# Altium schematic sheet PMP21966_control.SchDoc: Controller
size 431 x 279 mm; Date: Not shown in title block; ApprovedBy: Not shown in title block; CheckedBy: Not shown in title block; Author: Not shown in title block; CompanyName: Not shown in title block; DrawnBy: Tiger Z; Engineer: Not shown in title block; Organization: Not shown in title block; Address1: Not shown in title block; Address2: Not shown in title block; Address3: Not shown in title block; Address4: Not shown in title block; DocumentNumber: 5; Revision: Use project parameter SCH_Rev; SheetNumber: 1; SheetTotal: 3; PageSetup: Record=PageOptions¦CenterHorizontal=True¦CenterVertical=True¦PrintScale=1.00¦XCorrection=1.00¦YCorrection=1.00¦PrintKind=0¦BorderSize=5000000¦LeftOffset=0¦BottomOffset=0¦Orientation=2¦PaperLength=1000¦PaperWidth=1000¦Scale=100¦PaperSource=15¦PrintQuality=600¦MediaType=1¦DitherType=10¦PaperKind=Letter¦PrintScaleMode=1
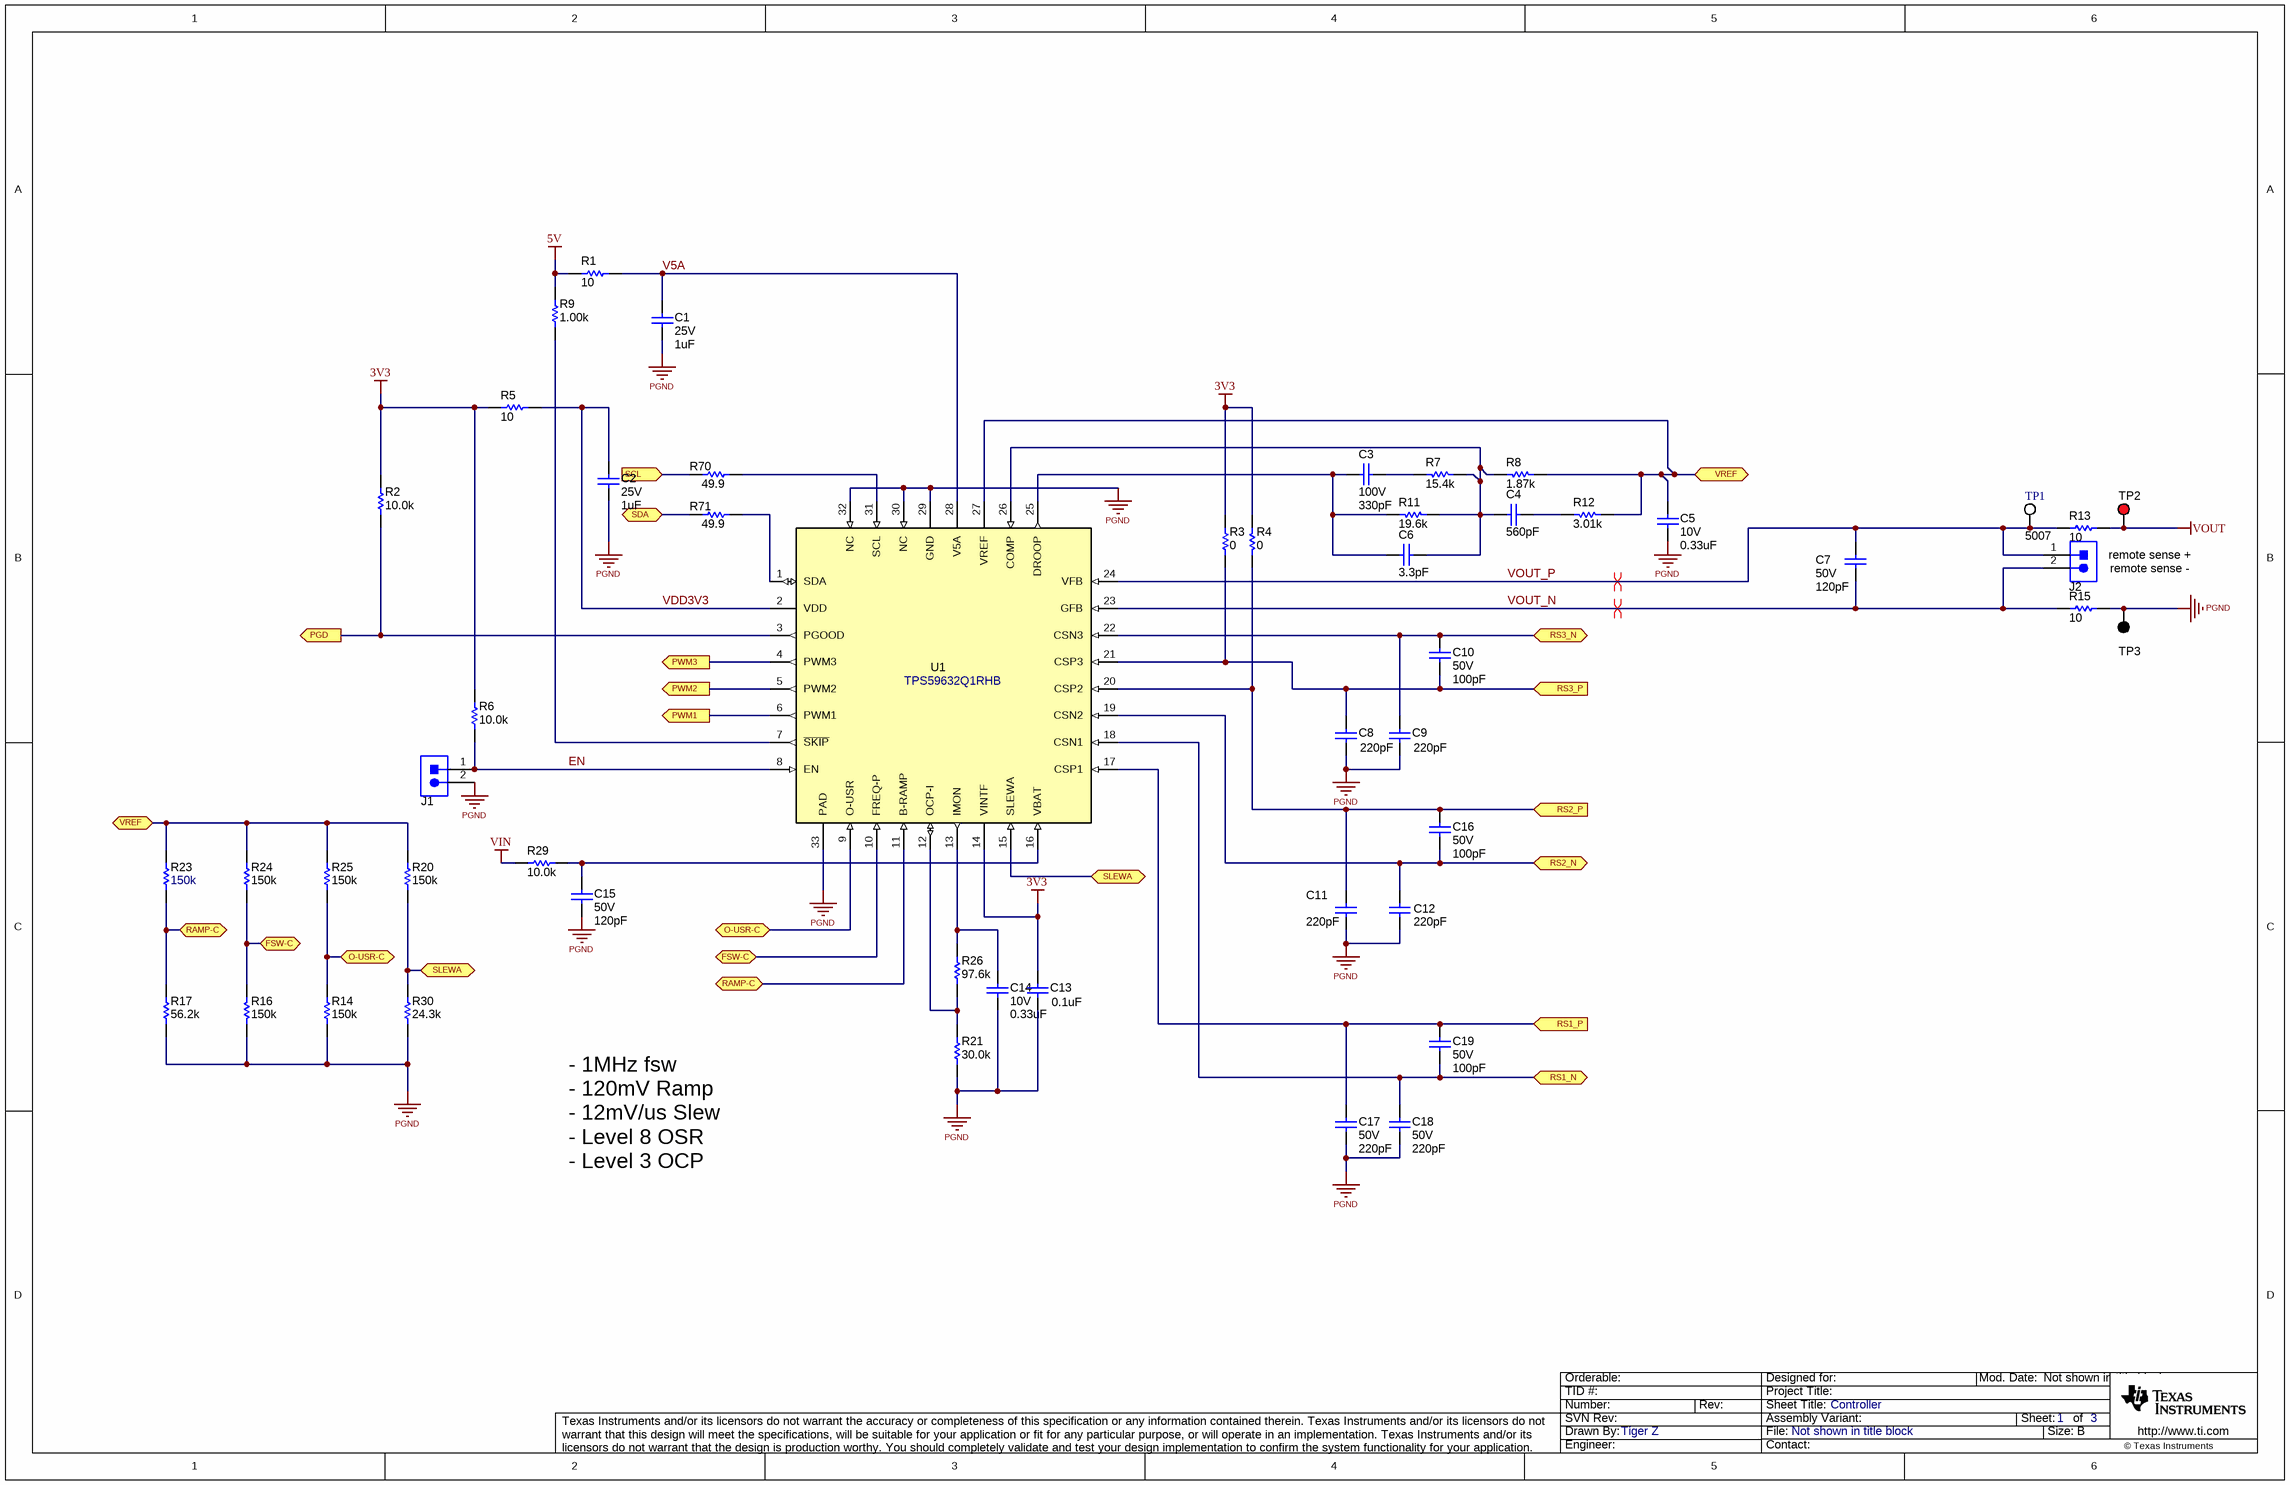
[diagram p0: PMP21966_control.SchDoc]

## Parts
C1  VDC_V: 25V  ValueDisplayed: 1uF  [0402S]  (hidden comment: GRM155R61E105KA12D)
C2  VDC_V: 25V  ValueDisplayed: 1uF  [0402S]  (hidden comment: GRM155R61E105KA12D)
C3  VDC_V: 100V  ValueDisplayed: 330pF  [0402S]  (hidden comment: GRM155R72A331KA01D)
C4  ValueDisplayed: 560pF  [0402S]  (hidden comment: GRM1555C1H561JA01D)
C5  VDC_V: 10V  ValueDisplayed: 0.33uF  [0402S]  (hidden comment: GRM155R61A334KE15D)
C6  ValueDisplayed: 3.3pF  [0402S]  (hidden comment: GRM1555C1E3R3CA01D)
C7  VDC_V: 50V  ValueDisplayed: 120pF  [0402S]  (hidden comment: GRM1555C1H121JA01D)
C8  ValueDisplayed: 220pF  [0402S]  (hidden comment: CGA2B2C0G1H221J050BA)
C9  ValueDisplayed: 220pF  [0402S]  (hidden comment: CGA2B2C0G1H221J050BA)
C10  VDC_V: 50V  ValueDisplayed: 100pF  [0402S]  (hidden comment: CC0402KRX7R9BB101)
C11  ValueDisplayed: 220pF  [0402S]  (hidden comment: CGA2B2C0G1H221J050BA)
C12  ValueDisplayed: 220pF  [0402S]  (hidden comment: CGA2B2C0G1H221J050BA)
C13  ValueDisplayed: 0.1uF  [0402S]  (hidden comment: CGA2B3X7R1H104K050BB)
C14  VDC_V: 10V  ValueDisplayed: 0.33uF  [0402S]  (hidden comment: GRM155R61A334KE15D)
C15  VDC_V: 50V  ValueDisplayed: 120pF  [0402S]  (hidden comment: GRM1555C1H121JA01D)
C16  VDC_V: 50V  ValueDisplayed: 100pF  [0402S]  (hidden comment: CC0402KRX7R9BB101)
C17  VDC_V: 50V  ValueDisplayed: 220pF  [0402S]  (hidden comment: CGA2B2C0G1H221J050BA)
C18  VDC_V: 50V  ValueDisplayed: 220pF  [0402S]  (hidden comment: CGA2B2C0G1H221J050BA)
C19  VDC_V: 50V  ValueDisplayed: 100pF  [0402S]  (hidden comment: CC0402KRX7R9BB101)
J1  HTSW-102-07-G-S  [Samtec_HTSW-102-07-G-S]  (value not drawn)
J2  HTSW-102-07-G-S  [Samtec_HTSW-102-07-G-S]  (value not drawn)
R1  ValueDisplayed: 10  [0402S]  (hidden comment: CRCW040210R0JNED)
R2  ValueDisplayed: 10.0k  [0402S]  (hidden comment: CRCW040210K0FKED)
R3  ValueDisplayed: 0  [0402S]  (hidden comment: CRCW04020000Z0ED)
R4  ValueDisplayed: 0  [0402S]  (hidden comment: CRCW04020000Z0ED)
R5  ValueDisplayed: 10  [0402S]  (hidden comment: CRCW040210R0JNED)
R6  ValueDisplayed: 10.0k  [0402S]  (hidden comment: CRCW040210K0FKED)
R7  ValueDisplayed: 15.4k  [0402S]  (hidden comment: CRCW040215K4FKED)
R8  Res_ohm: 1.87k  [0402S]  (hidden comment: CRCW04021K87FKED)
R9  ValueDisplayed: 1.00k  [0402S]  (hidden comment: CRCW04021K00FKED)
R11  ValueDisplayed: 19.6k  [0402S]  (hidden comment: CRCW040219K6FKED)
R12  ValueDisplayed: 3.01k  [0402S]  (hidden comment: CRCW04023K01FKED)
R13  ValueDisplayed: 10  [0402S]  (hidden comment: CRCW040210R0JNED)
R14  ValueDisplayed: 150k  [0402S]  (hidden comment: ERJ-2RKF1503X)
R15  ValueDisplayed: 10  [0402S]  (hidden comment: CRCW040210R0JNED)
R16  value 150k  [0402S]  (hidden comment: ERJ-2RKF1503X)
R17  ValueDisplayed: 56.2k  [0402S]  (hidden comment: CRCW040256K2FKED)
R20  ValueDisplayed: 150k  [0402S]  (hidden comment: ERJ-2RKF1503X)
R21  ValueDisplayed: 30.0k  [0402S]  (hidden comment: CRCW040230K0FKED)
R23  ValueDisplayed: 150k  [0402S]  (hidden comment: ERJ-2RKF1503X)
R24  ValueDisplayed: 150k  [0402S]  (hidden comment: ERJ-2RKF1503X)
R25  ValueDisplayed: 150k  [0402S]  (hidden comment: ERJ-2RKF1503X)
R26  ValueDisplayed: 97.6k  [0402S]  (hidden comment: CRCW040297K6FKED)
R29  ValueDisplayed: 10.0k  [0402S]  (hidden comment: CRCW040210K0FKED)
R30  ValueDisplayed: 24.3k  [0402S]  (hidden comment: CRCW040224K3FKED)
R70  ValueDisplayed: 49.9  [0402S]  (hidden comment: Resistor)
R71  ValueDisplayed: 49.9  [0402S]  (hidden comment: Resistor)
TP1  5007  [Keystone5002]
TP2  5000  [Keystone5000]  (value not drawn)
TP3  5001  [Keystone5001]  (value not drawn)
U1  TPS59632Q1RHB  [RSM0032B]

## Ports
FSW-C (bidir), O-USR-C (bidir), PGD (out), PWM1 (out), PWM2 (out), PWM3 (out), RAMP-C (bidir), RS1_N (bidir), RS1_P (in), RS2_N (bidir), RS2_P (in), RS3_N (bidir), RS3_P (in), SCL (in), SDA (bidir), SLEWA (bidir), VREF (bidir)

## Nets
3V3: C13.1 R2.2 R3.1 R4.1 R5.1 R6.2 U1.14(VINTF)
5V: R1.1 R9.2
PGND: C1.2 C2.2 C5.1 C8.1 C9.1 C11.2 C12.2 C13.2 C14.2 C15.1 C17.2 C18.2 J1.2 R14.1 R15.2 R16.2 R17.1 R21.1 R30.1 TP3.1 U1.29(GND) U1.30(NC) U1.32(NC) U1.33(PAD)
VIN: R29.1
VOUT: R13.2 TP2.1
EN: J1.1 R6.1 U1.8(EN)
FSW-C: R16.1 R24.1 U1.10(FREQ-P) ; port FSW-C
O-USR-C: R14.2 R25.1 U1.9(O-USR) ; port O-USR-C
PGD: R2.1 U1.3(PGOOD) ; port PGD
PWM1: U1.6(PWM1) ; port PWM1
PWM2: U1.5(PWM2) ; port PWM2
PWM3: U1.4(PWM3) ; port PWM3
RAMP-C: R17.2 R23.1 U1.11(B-RAMP) ; port RAMP-C
RS1_N: C18.1 C19.1 U1.18(CSN1) ; port RS1_N
RS1_P: C17.1 C19.2 U1.17(CSP1) ; port RS1_P
RS2_N: C12.1 C16.1 U1.19(CSN2) ; port RS2_N
RS2_P: C11.1 C16.2 R4.2 U1.20(CSP2) ; port RS2_P
RS3_N: C9.2 C10.2 U1.22(CSN3) ; port RS3_N
RS3_P: C8.2 C10.1 R3.2 U1.21(CSP3) ; port RS3_P
SCL: R70.1 ; port SCL
SDA: R71.1 ; port SDA
SLEWA: R20.1 R30.2 U1.15(SLEWA) ; port SLEWA
V5A: C1.1 R1.2 U1.28(V5A)
VDD3V3: C2.1 R5.2 U1.2(VDD)
VOUT_N: C7.2 J2.2 R15.1 U1.23(GFB)
VOUT_P: C7.1 J2.1 R13.1 TP1.1 U1.24(VFB)
VREF: C5.2 R8.2 R12.2 R20.2 R23.2 R24.2 R25.2 U1.27(VREF) ; port VREF
NetC3_1: C3.1 R7.2
NetC3_2: C3.2 C6.2 R11.1 U1.25(DROOP)
NetC4_1: C4.1 R12.1
NetC4_2: C4.2 C6.1 R7.1 R8.1 R11.2 U1.26(COMP)
NetC14_1: C14.1 R26.2 U1.13(IMON)
NetC15_2: C15.2 R29.2 U1.16(VBAT)
NetR9_1: R9.1 U1.7(~{SKIP})
NetR21_2: R21.2 R26.1 U1.12(OCP-I)
NetR70_2: R70.2 U1.31(SCL)
NetR71_2: R71.2 U1.1(SDA)

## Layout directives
differential pair: VOUT_N, VOUT_P

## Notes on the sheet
- remote sense +
- remote sense -
- - 1MHz fsw
  - 120mV Ramp
  - 12mV/us Slew
  - Level 8 OSR
  - Level 3 OCP

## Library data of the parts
C1 C2 = CMP-0006608-2: CAP, CERM, 1 uF, 25 V, +/- 10%, X5R, 0402; Manufacturer: MuRata; Cap_F: 1µF; SizeAreaWB_mm2: 3; SizeArea_mm2: 0.5; AEC Category: Q200; Value: 1uF; TaMax_C: 85°C; SizeZ_mm: 0.6; Polarized: N; TaMin_C: -55°C; U/M: EA; SizeX_mm: 1; Cap_Case: 0402; Value1: Unknown
C3 = CMP-0006707-2: CAP, CERM, 330 pF, 100 V, +/- 10%, X7R, 0402; Manufacturer: MuRata; SizeAreaWB_mm2: 3; SizeArea_mm2: 0.5; AEC Category: Q200; Value: 330pF; TaMax_C: 125°C; SizeZ_mm: 0.6; Polarized: N; TaMin_C: -55°C; U/M: EA; SizeX_mm: 1; Cap_Case: 0402; Value1: Unknown
C4 = CMP-0006479-2: CAP, CERM, 560 pF, 50 V, +/- 5%, C0G/NP0, 0402; Manufacturer: MuRata; TaMin_C: -55°C; Polarized: N; SizeAreaWB_mm2: 3; Value1: Unknown; U/M: EA; Value: 560pF; TaMax_C: 125°C; SizeZ_mm: 0.6; SizeX_mm: 1; SizeY_mm: 0.5; Cap_Case: 0402; Value2: 50V; CompType: Capacitor; AEC Category: Q200
C5 C14 = CMP-0006575-2: CAP, CERM, 0.33 uF, 10 V, +/- 10%, X5R, 0402; Manufacturer: MuRata; TaMin_C: -55°C; Polarized: N; SizeAreaWB_mm2: 3; Value1: Unknown; U/M: EA; Value: 0.33uF; TaMax_C: 85°C; SizeZ_mm: 0.6; SizeX_mm: 1; SizeY_mm: 0.5; Cap_Case: 0402; Cap_F: 330nF; AEC Category: Q200
C6 = CMP-0006383-2: CAP, CERM, 3.3 pF, 25 V, +/- 5%, C0G/NP0, 0402; Manufacturer: MuRata; TaMin_C: -55°C; Polarized: N; SizeAreaWB_mm2: 3; Value1: Unknown; U/M: EA; Value: 3.3pF; TaMax_C: 125°C; SizeZ_mm: 0.6; SizeX_mm: 1; SizeY_mm: 0.5; Cap_Case: 0402; Value2: 25V; CompType: Capacitor; AEC Category: Q200
C7 C15 = CMP-0006417-2: CAP, CERM, 120 pF, 50 V, +/- 5%, C0G/NP0, 0402; Manufacturer: MuRata; TaMin_C: -55°C; Polarized: N; SizeAreaWB_mm2: 3; Value1: Unknown; U/M: EA; Value: 120pF; TaMax_C: 125°C; SizeZ_mm: 0.6; SizeX_mm: 1; SizeY_mm: 0.5; Cap_Case: 0402; AEC Category: Q200
C8 C9 C11 C12 = CMP-0079606-1: CAP, CERM, 220 pF, 50 V,+/- 5%, C0G/NP0, AEC-Q200 Grade 1, 0402; Manufacturer: TDK; TaMin_C: -55°C; Polarized: N; SizeAreaWB_mm2: 3; U/M: EA; Value: 220pF; TaMax_C: 125°C; SizeZ_mm: 0.6; SizeX_mm: 1; SizeY_mm: 0.5; Cap_Case: 0402; Value2: 50V; CompType: Capacitor; AEC Qualified: Y; AEC Category: Q200
C10 C16 C19 = CMP-0006305-2: CAP, CERM, 100 pF, 50 V, +/- 10%, X7R, 0402; Manufacturer: Yageo America; TaMin_C: -55°C; Polarized: N; SizeAreaWB_mm2: 3; Value1: Unknown; U/M: EA; Value: 100pF; TaMax_C: 125°C; SizeZ_mm: 0.6; SizeX_mm: 1; SizeY_mm: 0.5; Cap_Case: 0402; AEC Category: Q200
C13 = CMP-0006325-2: CAP, CERM, 0.1 uF, 50 V, +/- 10%, X7R, AEC-Q200 Grade 1, 0402; Manufacturer: TDK; TaMin_C: -55°C; ESR_ohm: 0.039064; Polarized: N; SizeAreaWB_mm2: 3; Value1: 0.039064 ohm; U/M: EA; Value: 0.1uF; TaMax_C: 125°C; SizeZ_mm: 0.6; SizeX_mm: 1; SizeY_mm: 0.5; Cap_Case: 0402; Value2: 50V; CompType: Capacitor; AEC Qualified: Y; Cap_F: 100nF; IRMS_A: 8.14669dA; AEC Category: Q200
C17 = CMP-0079606-1: CAP, CERM, 220 pF, 50 V,+/- 5%, C0G/NP0, AEC-Q200 Grade 1, 0402; Manufacturer: TDK; TaMin_C: -55°C; Polarized: N; SizeAreaWB_mm2: 3; U/M: EA; Value: 220pF; TaMax_C: 125°C; SizeZ_mm: 0.6; SizeX_mm: 1; SizeY_mm: 0.5; Cap_Case: 0402; AEC Qualified: Y; AEC Category: Q200
C18 = CMP-0079606-1: CAP, CERM, 220 pF, 50 V,+/- 5%, C0G/NP0, AEC-Q200 Grade 1, 0402; Manufacturer: TDK; TaMin_C: -55°C; Polarized: N; SizeAreaWB_mm2: 3; U/M: EA; Value: 220pF; TaMax_C: 125°C; SizeZ_mm: 0.6; SizeX_mm: 1; SizeY_mm: 0.5; Cap_Case: 0402; CompType: Capacitor; AEC Qualified: Y; AEC Category: Q200
J1 J2 = CMP-0075483-1: Header, 100mil, 2x1, Gold, TH; Manufacturer: Samtec; Green_REACh: Passed; CT: False; Green_Lifecycle: Active; CNHeader: True
R1 R5 R13 R15 = CMP-0026827-3: RES, 10, 5%, 0.063 W, AEC-Q200 Grade 0, 0402; Manufacturer: Vishay-Dale; Power_W: 63mW; TempCo: 200 ppm/C; Value_Code: 10R0; Value: 10; EIA_Code: E24; SizeX_mm: 1; SizeY_mm: 0.5; SizeZ_mm: 0.6; Value2: 0.063W; AEC Qualified: Y; VDC_V: 50V; AEC Category: Q200; AEC Grade: 0
R2 = CMP-0025958-3: RES, 10.0 k, 1%, 0.063 W, AEC-Q200 Grade 0, 0402; Manufacturer: Vishay-Dale; Power_W: 63mW; TempCo: 100 ppm/C; Value_Code: 10k0; Value: 10.0k; EIA_Code: E96; Res_ohm: 10k; SizeX_mm: 1; SizeY_mm: 0.5; SizeZ_mm: 0.6; Value2: 0.063W; CompType: Resistor; AEC Qualified: Y; VDC_V: 50V; AEC Category: Q200; AEC Grade: 0
R3 R4 = CMP-0026822-3: RES, 0, 5%, 0.063 W, AEC-Q200 Grade 0, 0402; Manufacturer: Vishay-Dale; Power_W: 63mW; TempCo: 200 ppm/C; Value_Code: 0000; Value: 0; EIA_Code: E24; SizeX_mm: 1; SizeY_mm: 0.5; SizeZ_mm: 0.6; Value2: 0.063W; AEC Qualified: Y; VDC_V: 50V; AEC Category: Q200
R6 R29 = CMP-0025958-3: RES, 10.0 k, 1%, 0.063 W, AEC-Q200 Grade 0, 0402; Manufacturer: Vishay-Dale; Power_W: 63mW; TempCo: 100 ppm/C; Value_Code: 10k0; Value: 10.0k; EIA_Code: E96; Res_ohm: 10k; SizeX_mm: 1; SizeY_mm: 0.5; SizeZ_mm: 0.6; Value2: 0.063W; AEC Qualified: Y; VDC_V: 50V; AEC Category: Q200; AEC Grade: 0
R7 = CMP-0026028-3: RES, 15.4 k, 1%, 0.063 W, AEC-Q200 Grade 0, 0402; Manufacturer: Vishay-Dale; Power_W: 63mW; TempCo: 100 ppm/C; Value_Code: 15k4; Value: 15.4k; EIA_Code: E96; SizeX_mm: 1; SizeY_mm: 0.5; SizeZ_mm: 0.6; Value2: 0.063W; AEC Qualified: Y; VDC_V: 50V; AEC Grade: 0; AEC Category: Q200
R8 = CMP-0026097-2: RES, 1.87 k, 1%, 0.063 W, AEC-Q200 Grade 0, 0402; Manufacturer: Vishay-Dale; Power_W: 63mW; TempCo: 100 ppm/C; Value_Code: 1k87; Value: 1.87k; EIA_Code: E96; SizeX_mm: 1; SizeY_mm: 0.5; SizeZ_mm: 0.6; Value2: 0.063W; CompType: Resistor; AEC Qualified: Y; VDC_V: 50V; AEC Category: Q200; AEC Grade: 0
R9 = CMP-0026071-3: RES, 1.00 k, 1%, 0.063 W, AEC-Q200 Grade 0, 0402; Manufacturer: Vishay-Dale; Power_W: 63mW; TempCo: 100 ppm/C; Value_Code: 1k00; Value: 1.00k; EIA_Code: E96; Res_ohm: 1k; SizeX_mm: 1; SizeY_mm: 0.5; SizeZ_mm: 0.6; Value2: 0.063W; AEC Qualified: Y; VDC_V: 50V; AEC Category: Q200; AEC Grade: 0
R11 = CMP-0026068-3: RES, 19.6 k, 1%, 0.063 W, AEC-Q200 Grade 0, 0402; Manufacturer: Vishay-Dale; Power_W: 63mW; TempCo: 100 ppm/C; Value_Code: 19k6; Value: 19.6k; EIA_Code: E96; SizeX_mm: 1; SizeY_mm: 0.5; SizeZ_mm: 0.6; Value2: 0.063W; CompType: Resistor; AEC Qualified: Y; VDC_V: 50V; AEC Category: Q200; AEC Grade: 0
R12 = CMP-0026329-2: RES, 3.01 k, 1%, 0.063 W, AEC-Q200 Grade 0, 0402; Manufacturer: Vishay-Dale; Power_W: 63mW; TempCo: 100 ppm/C; Value_Code: 3k01; Value: 3.01k; EIA_Code: E96; SizeX_mm: 1; SizeY_mm: 0.5; SizeZ_mm: 0.6; Value2: 0.063W; AEC Qualified: Y; VDC_V: 50V; AEC Category: Q200; AEC Grade: 0
R14 = CMP-0026669-1: RES, 150 k, 1%, 0.1 W, AEC-Q200 Grade 0, 0402; Manufacturer: Panasonic; Power_W: 100mW; TempCo: 100 ppm/C; Value: 150k; EIA_Code: E96; SizeX_mm: 1; SizeY_mm: 0.5; SizeZ_mm: 0.6; Value2: 0.1W; AEC Qualified: Y; VDC_V: 50V; AEC Category: Q200; AEC Grade: 0; U/M: EA
R16 = CMP-0026669-1: RES, 150 k, 1%, 0.1 W, AEC-Q200 Grade 0, 0402; Manufacturer: Panasonic; Power_W: 100mW; TempCo: 100 ppm/C; U/M: EA; EIA_Code: E96; SizeX_mm: 1; SizeY_mm: 0.5; SizeZ_mm: 0.6; Value2: 0.1W; CompType: Resistor; AEC Qualified: Y; VDC_V: 50V; AEC Grade: 0; AEC Category: Q200
R17 = CMP-0026453-2: RES, 56.2 k, 1%, 0.063 W, AEC-Q200 Grade 0, 0402; Manufacturer: Vishay-Dale; Power_W: 63mW; TempCo: 100 ppm/C; Value_Code: 56k2; Value: 56.2k; EIA_Code: E96; SizeX_mm: 1; SizeY_mm: 0.5; SizeZ_mm: 0.6; Value2: 0.063W; AEC Qualified: Y; VDC_V: 50V; AEC Category: Q200; AEC Grade: 0
R20 R23 R25 = CMP-0026669-1: RES, 150 k, 1%, 0.1 W, AEC-Q200 Grade 0, 0402; Manufacturer: Panasonic; Power_W: 100mW; TempCo: 100 ppm/C; U/M: EA; Value: 150k; EIA_Code: E96; SizeX_mm: 1; SizeY_mm: 0.5; SizeZ_mm: 0.6; Value2: 0.1W; CompType: Resistor; AEC Qualified: Y; VDC_V: 50V; AEC Grade: 0; AEC Category: Q200
R21 = CMP-0078244-2: RES, 30.0 k, 1%, 0.063 W, AEC-Q200 Grade 0, 0402; Manufacturer: Vishay-Dale; Power_W: 63mW; TempCo: 100 ppm/C; Value_Code: 30k0; Value: 30.0k; Res_ohm: 30k; SizeX_mm: 1; SizeY_mm: 0.5; SizeZ_mm: 0.6; Value2: 0.063W; AEC Qualified: Y; VDC_V: 50V; AEC Category: Q200; AEC Grade: 0; Green_Lifecycle: Active; Green_REACh: Passed
R24 = CMP-0026669-1: RES, 150 k, 1%, 0.1 W, AEC-Q200 Grade 0, 0402; Manufacturer: Panasonic; Power_W: 100mW; TempCo: 100 ppm/C; U/M: EA; Value: 150k; EIA_Code: E96; SizeX_mm: 1; SizeY_mm: 0.5; SizeZ_mm: 0.6; Value2: 0.1W; AEC Qualified: Y; VDC_V: 50V; AEC Grade: 0; AEC Category: Q200
R26 = CMP-0026617-3: RES, 97.6 k, 1%, 0.063 W, AEC-Q200 Grade 0, 0402; Manufacturer: Vishay-Dale; Power_W: 63mW; TempCo: 100 ppm/C; Value_Code: 97k6; Value: 97.6k; EIA_Code: E96; SizeX_mm: 1; SizeY_mm: 0.5; SizeZ_mm: 0.6; Value2: 0.063W; AEC Qualified: Y; VDC_V: 50V; AEC Category: Q200; AEC Grade: 0
R30 = CMP-0026195-2: RES, 24.3 k, 1%, 0.063 W, AEC-Q200 Grade 0, 0402; Manufacturer: Vishay-Dale; Power_W: 63mW; TempCo: 100 ppm/C; Value_Code: 24k3; Value: 24.3k; EIA_Code: E96; SizeX_mm: 1; SizeY_mm: 0.5; SizeZ_mm: 0.6; Value2: 0.063W; CompType: Resistor; AEC Qualified: Y; VDC_V: 50V; AEC Category: Q200; AEC Grade: 0
R70 R71 = CMP-0026404-2: RES, 49.9, 1%, 0.063 W, AEC-Q200 Grade 0, 0402; PartNumber: CRCW040249R9FKED; Manufacturer: Vishay-Dale; Value: 49.9; Value_Code: 49R9; Power_W: 63mW; Value2: 0.063W; VDC_V: 50V; TempCo: 100 ppm/C; EIA_Code: E96; SizeArea_mm2: 0.5; SizeX_mm: 1; SizeZ_mm: 0.6; AEC Category: Q200; AEC Qualified: Y; AEC Grade: 0
TP1 = CMP-0055139-1: Test Point, Miniature, White, TH; Manufacturer: Keystone; CNHeader: FALSE; Green_Lifecycle: Active; Green_REACh: Passed; ContactFinish: Silver; CT: TRUE
TP2 = CMP-0055137-1: Test Point, Miniature, Red, TH; Manufacturer: Keystone; CNHeader: FALSE; Green_Lifecycle: Active; Green_REACh: Passed; ContactFinish: Silver; CT: TRUE
TP3 = CMP-0055138-1: Test Point, Miniature, Black, TH; Manufacturer: Keystone; CNHeader: FALSE; ContactFinish: Silver; CT: TRUE; Green_Lifecycle: Active; Green_REACh: Passed
U1 = CMP-0013985-3: 3-2-1 Phase D-Cap+ Step-Down Driverless Controller for Tegra CPUs with Serial VID Control and DVFS, RSM0032B (VQFN-32); Alternate Manufacturer: Texas Instruments; SizeAreaWB_mm2: 25; SizeZ_mm: 1; SizeX_mm: 4; SizeArea_mm2: 16; CompType: IC; AEC Qualified: N; AEC Category: Q200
